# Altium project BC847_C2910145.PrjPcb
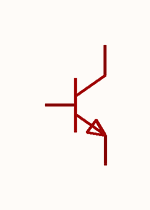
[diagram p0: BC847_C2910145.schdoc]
1 sheet, 1 parts. Net scope: global (net labels, ports and power ports of the same name join across sheets).

## Sheet BC847_C2910145.schdoc
size 127 x 101 mm

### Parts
Q?  bc847(range:200-450)  [SOT-23-3_L2.9-W1.3-P1.90-LS2.4-BR]  (value not drawn)

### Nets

Not connected (* = marked no-connect by the designer): Q? 1(B) 2(E) 3(C)

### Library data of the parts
Q? = bc847(range:200-450): 晶体管类型:NPN;集电极电流(Ic):100mA;集射极击穿电压(Vceo):45V;耗散功率(Pd):200mW;直流电流增益(hFE):450;; Manufacturer: CJ(江苏长电/长晶); Symbol: BC847_C2910145; AddInBom: yes; ModelId: c62791f0466c4ae2a892c056b845b0ca; ModelName: SOT-23-3P_L2.9-W1.3-H1.0-LS2.4-P0.95; ModelTransform: 98.425,114.173,0,180,0,0,0.0005,-0.0005,0; type: NPN; Current - Collector(Ic): 100mA; Collector - Emitter Voltage VCEO: 45V; Pd - Power Dissipation: 200mW; DC Current Gain: 450; Transition frequency(fT): 100MHz; Current - Collector Cutoff: 100nA; Vce Saturation(VCE(sat)): 500mV; Emitter-Base Voltage(Vebo): 6V; Number: 1个NPN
